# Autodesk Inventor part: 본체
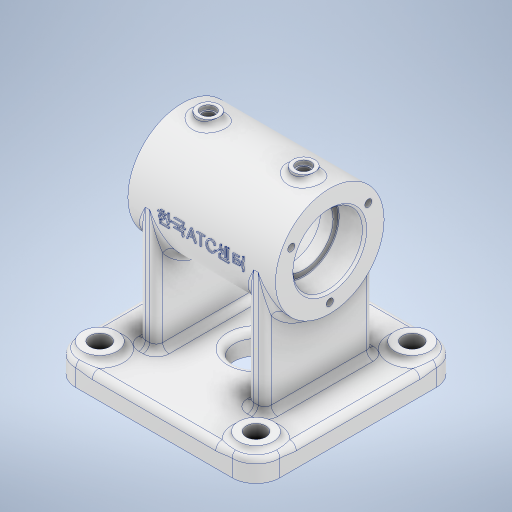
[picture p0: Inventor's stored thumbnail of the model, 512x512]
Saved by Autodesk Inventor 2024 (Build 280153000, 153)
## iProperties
Created: 2025-10
Part Number: 본체
Material: 알루미늄 6061
Document SubType Name: Modeling
Designer: EDU03
Density: 2.7 g/cm^3
Appearance: 알루미늄 - 평지
Mass: 505.839 g
Surface Area: 503.745 cm^2
Volume: 187.348 cm^3
Author: EDU03
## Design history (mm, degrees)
sketch "스케치1"
  geometry: L1 (47, -47)-(-47, -47); L2 (-47, -47)-(-47, 47); L3 (-47, 47)-(47, 47); L4 (47, 47)-(47, -47); 3 further points
  constraints: 8 end point, 2 midpoint, 2 parallel, 1 horizontal, 1 horizontal alignment, 1 perpendicular, 1 vertical alignment
  dimensions: "d0" = 94 distance of L1.start L1.end; "d1" = 94 distance of L3.end L1.start
extrude "돌출1" new body sketch "스케치1" distance "d2" = 10; taper "d3" = 0 deg
node "작업 평면1"
sketch "스케치2"
  geometry: L1 (0, 47)-(0, -47) reference; C1 r 25 at (66, 0); 2 further points
  constraints: 1 centre point, 1 horizontal alignment, 1 midpoint
  dimensions: "d5" = 66 distance from line of L1 C1.centre; "d6" = 50 diameter of C1
extrude "돌출2" join sketch "스케치2" stored distance "d7" = 68; taper "d8" = 0 deg
sketch "스케치4"
  geometry: L1 (-29, 25)-(-21, 25); L2 (-21, 25)-(-21, -25); L3 (-21, -25)-(-29, -25); L4 (-29, -25)-(-29, 25); L5 (21, 25)-(29, 25); L6 (29, 25)-(29, -25); L7 (29, -25)-(21, -25); L8 (21, -25)-(21, 25); L9 (-21, 0)-(21, 0); 3 further points
  constraints: 18 end point, 4 midpoint, 4 parallel, 3 perpendicular, 2 horizontal, 2 horizontal alignment, 1 coincident, 1 point on line
  dimensions: "d14" = 50 distance of L3.end L1.start; "d15" = 8 distance of L1.start L1.end; "d16" = 8 distance of L5.start L5.end; "d17" = 42 distance between parallel lines of L8 L2
extrude "돌출3" join sketch "스케치4" stored distance "d18" = 68; taper "d19" = 0 deg
sketch "스케치5"
  geometry: 1 further point
fillet "모깎기1" dims "d20" = 11
sketch "스케치6"
  geometry: C1 r 8 at (-36, 36); C2 r 8 at (36, 36); C3 r 8 at (36, -36); C4 r 8 at (-36, -36); A1 r 11 centre (-36, 36) between (-36, 47) and (-47, 36) reference; A2 r 11 centre (36, 36) between (47, 36) and (36, 47) reference; A3 r 11 centre (36, -36) between (36, -47) and (47, -36) reference; A4 r 11 centre (-36, -36) between (-47, -36) and (-36, -47) reference; 1 further point
  constraints: 4 centre point, 4 coincident
  dimensions: "d21" = 16 diameter of C1; "d22" = 16 diameter of C2; "d23" = 16 diameter of C3; "d24" = 16 diameter of C4
extrude "돌출4" join sketch "스케치6" distance "d25" = 3; taper "d26" = 0 deg
sketch "스케치7"
  geometry: C1 r 8 at (0, 0) reference; C2 r 8 at (72, 0) reference; C3 r 8 at (72, 72) reference; C4 r 8 at (0, 72) reference; 5 further points
  constraints: 4 coincident
hole "구멍1" sketch "스케치7" at (0, 0), (72, 0), (72, 72), (0, 72) diameter "d27" = 9; stored, may be unused: countersink angle "d31" = 90 deg, drill point angle "d33" = 118 deg; dims "d28" = 6, "d29" = 4, "d30" = 2, "d32" = 8
sketch "스케치8"
  geometry: C1 r 10 at (0, 0); 1 further point
  constraints: 1 centre point, 1 coincident
  dimensions: "d34" = 20 diameter of C1
extrude "돌출5" cut sketch "스케치8" extent not by distance; stored distance "d35" = 0; taper "d36" = 0 deg
sketch "스케치9"
  geometry: L1 (-34, 91)-(-34, 41) reference; L2 (-34, 66)-(34, 66); L3 (34, 41)-(34, 91) reference; L4 (-34, 66)-(-22, 66); L5 (-22, 66)-(-22, 81.7); L6 (-22.3, 82)-(-34, 82); L7 (-34, 82)-(-34, 66); L8 (-22, 66)-(-16.258, 66); L9 (-16.258, 66)-(-16.258, 79.5); L10 (-16.258, 79.5)-(-22, 79.5); L11 (-22, 79.5)-(-22, 66); L12 (-16.258, 79.5)-(-5, 86); L13 (-5, 86)-(5, 86); L14 (5, 86)-(16.258, 79.5); L15 (34, 66)-(22, 66); L16 (22, 66)-(22, 81.7); L17 (22.3, 82)-(34, 82); L18 (34, 82)-(34, 66); L19 (22, 66)-(16.258, 66); L20 (16.258, 66)-(16.258, 79.5); L21 (16.258, 79.5)-(22, 79.5); L22 (22, 79.5)-(22, 66); A1 r 0.3 centre (-22.3, 81.7) between (-22, 81.7) and (-22.3, 82); A2 r 0.3 centre (22.3, 81.7) between (22.3, 82) and (22, 81.7); 9 further points
  constraints: 40 end point, 8 parallel, 5 horizontal, 4 midpoint, 4 perpendicular, 4 point on circle, 4 point on line, 4 tangent, 2 centre point, 1 equal radius, 1 vertical alignment
  dimensions: "d37" = 12 distance of point (-22, 82) L6.end; "d38" = 30 deg angle of L2 L12; "d40" = 30 deg angle of L2 L14; "d41" = 32 diameter of L6 L2; "d42" = 10 distance of L13.end L12.end; "d43" = 32 diameter of L17 L2; "d44" = 27 diameter of L21 L2; "d45" = 27 diameter of L10 L2; "d46" = 40 diameter of L13 L2; "d47" = 12 distance of point (22, 82) L17.end; "d48" = 0.3 radius of A1
revolve "회전1" sketch "스케치9" stored, may be unused: angle "d49" = 90 deg
node "작업 평면2"
sketch "스케치10"
  geometry: L1 (34, -25)-(34, 25) reference; L2 (-34, 25)-(-34, -25) reference; C1 r 5 at (22, 0); C2 r 5 at (-22, 0); 1 further point
  constraints: 2 centre point, 2 horizontal alignment
  dimensions: "d51" = 12 distance from line of L1 C1.centre; "d52" = 12 distance from line of L2 C2.centre; "d53" = 10 diameter of C1; "d54" = 10 diameter of C2
extrude "돌출6" join sketch "스케치10" stored distance "d55" = 10; taper "d56" = 0 deg
sketch "스케치11"
  geometry: C1 r 5 at (0, 0) reference; C2 r 5 at (44, 0) reference; 3 further points
  constraints: 2 coincident
hole "구멍2" sketch "스케치11" at (0, 0), (44, 0) diameter "d57" = 5.1881; stored, may be unused: countersink angle "d61" = 90 deg, drill point angle "d63" = 118 deg; dims "d58" = 25.25, "d59" = 6.6, "d60" = 2, "d62" = 30.5
sketch "스케치12"
  geometry: C1 r 25 at (0, 0) reference; A1 r 20.5 centre (0, 0) between (-17.754, 10.25) and (17.754, 10.25); 2 further points
  constraints: 3 point on circle, 1 centre point, 1 coincident, 1 vertical alignment
  dimensions: "d64" = 41 diameter of A1; "d65" = 120 deg dimension on A1.centre A1.end point (0, -20.5); "d66" = 120 deg dimension on A1.centre A1.start point (0, -20.5)
hole "구멍3" sketch "스케치12" at (-17.754, 10.25), (17.754, 10.25), (0, -20.5) diameter "d67" = 3.242; stored, may be unused: countersink angle "d71" = 90 deg, drill point angle "d73" = 118 deg; dims "d68" = 8, "d69" = 6.6, "d70" = 2, "d72" = 10
node "작업 평면3"
node "작업 평면4"
sketch "스케치13"
  geometry: C1 r 6 at (0, 0); 2 further points
  constraints: 2 coincident, 1 centre point
  dimensions: "d75" = 12 diameter of C1
extrude "돌출7" join sketch "스케치13" stored distance "d76" = 10; taper "d77" = 0 deg
sketch "스케치14"
  geometry: C1 r 6 at (0, 0) reference; 2 further points
  constraints: 1 coincident
hole "구멍4" sketch "스케치14" at (0, 0) diameter "d78" = 5.1881; stored, may be unused: countersink angle "d82" = 90 deg, drill point angle "d84" = 0 deg; dims "d79" = 18, "d80" = 4, "d81" = 2, "d83" = 24
fillet "모깎기2" dims "d85" = 3
fillet "모깎기3" dims "d86" = 3
fillet "모깎기4" dims "d87" = 3
fillet "모깎기5" dims "d88" = 3
fillet "모깎기6" dims "d89" = 3
node "작업 평면5"
sketch "스케치15"
  geometry: L1 (-36, 0)-(36, 0) reference; 2 further points
  constraints: 1 vertical alignment, 1 other
  dimensions: "d91" = 66 distance from line of L1 point (0, 66)
feature "엠보싱1" sketch "스케치15" dims "d14" = 50, "d15" = 8, "d16" = 8, "d17" = 42, "d92" = 0.5, "d93" = 0
fillet "모깎기7" dims "d94" = 3
chamfer "모따기1" distance "d95" = 1; stored, may be unused: second distance "d96" = 2, angle "d97" = 45 deg
fillet "모깎기8" dims "d98" = 3
fillet "모깎기9" dims "d99" = 3
feature "ϣ耀ϥ耀ϧ耀ϩ耀ϫ耀ϭ耀ϯ耀ϱ耀" dims "d0" = 94, "d1" = 94, "d2" = 10, "d3" = 0, "d4" = 66, "d5" = 66, "d6" = 50, "d7" = 68, "d8" = 0, "d14" = 50, "d15" = 8, "d16" = 8, "d17" = 42, "d18" = 68, "d19" = 0, "d20" = 11, "d21" = 16, "d22" = 16, "d23" = 16, "d24" = 16, "d25" = 3, "d26" = 0, "d27" = 9, "d28" = 6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
node "솔리드1"
mirror "미러1"
feature "A9D066F2-1C7D-4E18-AEED-F7BC21143FA4" dims "d67" = 3.242, "d68" = 8, "d69" = 6.6, "d70" = 2, "d71" = 90 deg, "d72" = 10, "d73" = 118 deg
